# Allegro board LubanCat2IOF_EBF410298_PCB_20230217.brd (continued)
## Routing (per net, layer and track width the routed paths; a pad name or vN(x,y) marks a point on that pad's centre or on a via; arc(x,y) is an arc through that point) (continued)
VCC3V3_SD: length 187.3
  TOP w0.305: J38.17 18.6,61.13 18.86,60.87 ; v1(22.45,14.04) 22.45,26.87 18.86,30.46 18.86,60.87 ; 18.86,60.87 19.1,61.11 J38.19 ; v1(132.66,13.36) 132.66,23.52 133.38,24.23 v1(136.66,24.23) 140.23,24.23 v1(140.94,23.52)
  BOTTOM w0.305: v1(132.66,13.36) 132.05,13.97 115.14,13.97 112.57,11.4 25.1,11.4 v1(22.45,14.04) ; C28.1 v1(136.66,24.23) ; J4.4 v1(140.94,23.52) C30.1
VCC5V0_SYS: length 188.1
  TOP w0.305: 10.46,61.36 10.46,63.8 10.03,64.23 8.76,64.23 8.46,64.54 8.46,70.8 7.85,71.41 C24.2 R11.2
  ART04 w0.305: v1(7.62,59.61) 5.36,59.61 4.75,60.22 4.75,87.3 5.51,88.06 8.81,88.06 9.4,88.64 9.4,94 10.13,94.74 17.55,94.74 18.87,96.06 29.72,96.06 30.33,96.67 30.33,97.94 30.94,98.55 46.91,98.55 47.65,97.81 54.1,97.81 54.94,98.65 108.08,98.65 108.51,98.22 109.86,98.22 110.55,98.9 113.61,98.9 114.05,98.47 118.31,98.47 118.61,98.77 125.15,98.77 125.58,98.34 128.67,98.34 128.86,98.53 131.87,98.53 132.79,97.61 v1(135.52,97.61)
  BOTTOM w0.305: R4.1 v1(135.52,97.61)
VCC5V0_USB: length 13.2
  TOP w0.305: v1(11.53,73.21) C140.2 R235.2
  ART04 w0.305: v1(129.09,96.97) 129.07,96.99 v1(125.52,96.99)
  BOTTOM w0.305: C159.1 11.55,73.22 v1(11.53,73.21)
  vias: v1(14.07,77.26) v1(14.07,76.26) v1(15.07,77.26) v1(15.07,76.26) v1(31.12,86.66) v1(31.12,85.66) v1(32.12,86.66) v1(32.12,85.66) v1(117.47,82.44) v1(118.47,82.44) v1(119.47,82.44) v1(124.52,97.97) v1(124.52,96.97) v1(129.09,97.97) v1(130.09,96.99)
VCC5V0_USB20_HOST2: length 11.6
  BOTTOM w0.508: U24.1 125.41,93.59 C144.1 C145.1 125.34,91.72 125.65,91.41 128.14,91.41 128.7,90.85 128.7,90.14 129.31,89.53 129.31,87.72 J19.10
VCC5V0_USB20_HUB: length 38.3
  TOP w0.305: J20.7 111.1,90.42 110.8,90.72 103.81,90.72 103.5,91.03 103.5,93.72 103.2,94.03 101.22,94.03 100.71,94.53 100.71,96.9 v1(101.47,97.66)
  TOP w0.508: J20.7 J20.1 111.25,85.35 C164.1 C165.1 C162.1 C161.1 114.37,81.39 U29.1
  BOTTOM w0.305: C155.1 101.46,97.72 101.47,97.71 ; 101.47,97.71 v1(101.47,97.66) ; 101.47,97.71 103.51,97.71 104,98.21 C154.1 104.61,97.74 106.07,97.74 106.45,97.36 U28.19
VCC5V0_USB30_HOST: length 5.1
  BOTTOM w0.508: U26.1 129.98,93.59 C148.1 C149.1 129.91,90.45 J19.1
VCC_1V8: length 128.7
  TOP w0.305: L14.2 v1(79.81,39.8) ; Q1.1 v1(28.64,27.5) ; U6.8 v1(33.02,34.77) ; J38.13 17.6,61.13 17.86,60.87 18.1,61.11 J38.15 ; L10.2 v1(60.29,38.62) ; Q2.1 v1(24.83,27.5)
  TOP w0.381: v1(16.91,36.29) 16.91,58.86 17.86,59.82 17.86,60.87
  ART03 w0.381: v1(60.29,38.62) 60.29,39.09 59.52,39.85 35.71,39.85 34.9,39.04 34.9,36.65 v1(33.02,34.77) 33.02,28.9 32.64,28.52 29.65,28.52 v1(28.64,27.5)
  ART04 w0.381: v1(60.29,38.62) 60.29,37.84 60.9,37.23 79.2,37.23 79.81,37.84 v1(79.81,39.8)
  BOTTOM w0.305: v1(28.64,27.5) 28.64,27.04 R45.1 28.48,25.98 25.7,25.98 25.28,26.4 R46.1 24.83,27.04 v1(24.83,27.5)
  BOTTOM w0.381: C22.1 v1(33.02,34.77) C23.1 ; 20.33,35.75 19.79,36.29 v1(16.91,36.29) ; 20.33,35.75 R24.1 ; 20.33,35.75 20.9,36.32 31.72,36.32 32.21,35.84 32.21,34.81 C23.1 ; C23.1 R25.1
VCCA_1V8: length 23.4
  TOP w0.305: J38.14 17.85,71.61 v1(18.1,71.87) 18.35,71.62 J38.16
  BOTTOM w0.305: R219.1 26.27,70.78 25.66,70.17 25.66,65.76 25.08,65.18 22.58,65.18 21.97,65.79 21.97,70.56 21.36,71.17 18.81,71.17 v1(18.1,71.87)
VCCIO_ACODEC: length 45.7
  TOP w0.305: J38.23 20.1,63.64 v1(19.84,63.9) 19.6,63.67 J38.21 ; v1(38.18,77.39) 37.77,76.98 31.29,76.98 30.63,76.32 v1(25.85,76.32)
  BOTTOM w0.305: v1(25.85,76.32) 25.85,74.67 25.15,73.96 24.13,73.96 22.86,72.69 17.75,72.69 17.14,72.08 17.14,70.4 18.03,69.52 18.03,64.51 18.64,63.9 v1(19.84,63.9) ; R213.1 v1(38.18,77.39) 38.18,84.71 R210.1
VDD_3V3: length 85.3
  TOP w0.305: v1(59.29,38.62) 59.29,41.46 L11.2 ; L12.2 v1(58.38,52.31) ; C21.1 v1(4.57,23.8) 4.57,22.93 4.27,22.63 3.38,22.63 3.07,22.93 U12.5 ; R6.2 C14.2 9.91,43.47 10.46,42.92 10.46,33.42 ; R33.1 v1(41.91,56.91) ; L7.2 v1(59.94,20.75) ; U9.5 v1(33.27,20.58) ; U35.5 v1(144.08,64.88) ; U10.5 v1(25.78,20.58) ; U4.5 7.26,22.96 7.57,22.65 8.46,22.65 8.76,22.96 C17.1 v1(9.53,24.57) ; L15.2 v1(79.81,42.46) ; L6.1 v1(40.64,23.41) ; R35.1 v1(43.43,56.91) ; L5.1 v1(48.26,23.41) ; L16.2 v1(78.83,52.31)
  TOP w0.508: 12,16.43 J3.5 12,14.97
  PWR05 w0.508: J3.5 12.73,15.7 ; J3.5 11.27,15.7 ; J3.5 12,16.43 ; J3.5 12,14.97
  BOTTOM w0.305: R47.1 v1(30.47,24.93) ; v1(1.8,52.51) 4.13,52.51 4.44,52.82 R2.2 ; 62.12,73.83 62.42,73.53 Q8.1 61.97,72.4 R181.1 ; 62.12,73.83 62.87,74.58 v1(62.87,78.66) ; 62.12,73.83 59.42,73.83 59.12,73.53 ; C40.1 v1(25.78,20.58) ; R178.1 58.67,72.4 Q6.1 59.12,73.53 ; 59.12,73.53 58.81,73.83 56.63,73.83 56.32,73.53 56.32,71.98 56.02,71.67 R180.1 ; R72.1 v1(15.71,87.85) ; R48.1 v1(24.9,24.93) ; v1(7.65,78.82) 7.65,77.69 7.35,77.38 R236.2 ; R31.1 v1(140.22,97.35) ; C37.1 v1(33.27,20.58) ; R66.2 v1(150.5,95.86) ; R146.1 93.48,61.8 94.08,62.4 96.03,62.4 96.64,61.8 R147.1 96.64,60.94 v1(96.6,60.91) ; R32.1 v1(146.81,95.83)
  vias: v1(9.02,32.64) v1(9.02,31.64) v1(10.02,32.64) v1(10.02,31.64) v1(11.02,32.64) v1(11.02,31.64) v1(20.22,79.94) v1(20.22,78.94) v1(95.31,21.68) v1(96.31,21.68) v1(142.64,13.3) v1(142.64,12.3) v1(143.08,65.88) v1(143.64,13.3) v1(143.64,12.3) v1(144.08,65.88) v1(144.71,41.91) v1(145.71,41.91)
VDD_3V3_EDP_LCD: length 32.5
  TOP w0.305: J29.12 152.81,22.05 153.03,22.27 152.76,22.55 J29.13 ; R187.1 v1(149.22,20.75)
  TOP w0.508: 153.03,22.27 v1(153.39,22.27) 155.57,22.27 156.08,21.76 156.08,13.69 155.45,13.05 149.1,13.05 148.59,13.56 C184.1 C183.1 147.5,14.21 U37.1
  BOTTOM w0.305: v1(153.39,22.27) 153.39,21.05 153.09,20.75 v1(149.22,20.75)
VDD_3V3_EDP_TP: length 29
  TOP w0.305: R193.1 R194.1 C203.1 v1(99.31,18.61)
  BOTTOM w0.381: v1(99.31,18.61) v1(99.31,17.61) 100.08,16.84 100.08,13.23 100.84,12.47 112.19,12.47 112.95,13.23 J28.1
VDD_5V: length 62.1
  TOP w0.305: U10.3 v1(27.05,22.95) ; 10.06,47.37 10.06,57.14 9.75,57.44 C2.2 R1.2 ; v1(144.08,68.72) 143.98,68.82 U36.5 ; U34.5 v1(144.08,60.82) ; U33.5 v1(144.08,57.52) ; U9.3 v1(34.54,22.95)
  TOP w0.508: J3.3 16,16.43 ; J3.3 16.73,15.7 ; J3.3 16,14.97 ; J3.3 15.27,15.7
  BOTTOM w0.305: 49.68,77.69 51.05,76.32 51.05,74.24 51.51,73.78 54.64,73.78 Q7.1 ; 27.05,22.2 v1(27.05,22.95) C41.1 ; 27.05,22.2 27.63,21.61 34.11,21.61 34.54,22.04 v1(34.54,22.95) C38.1 ; 27.05,22.2 26.44,21.59 16.61,21.59 16,20.98 J3.3
  vias: v1(9.02,46.61) v1(9.02,45.61) v1(10.02,46.61) v1(10.02,45.61) v1(11.02,46.61) v1(11.02,45.61) v1(28.38,81.72) v1(29.38,81.72) v1(29.38,80.72) v1(47.01,78.63) v1(47.01,77.63) v1(48.01,78.63) v1(48.01,77.63) v1(119.86,65.68) v1(119.86,64.68) v1(120.86,65.68) v1(120.86,64.68) v1(121.86,65.68) v1(121.86,64.68) v1(133.13,59.59) v1(133.13,58.59) v1(134.13,59.59) v1(134.13,58.59) v1(135.1,59.59) v1(135.13,58.59) v1(143.08,69.72) v1(143.08,61.82) v1(143.08,58.52) v1(143.59,37.24) v1(144.08,69.72) v1(144.08,61.82) v1(144.08,58.52) v1(144.71,38.24) v1(144.71,37.24)
VDD_CAM0_5V: length 9.2
  TOP w0.508: C171.1 C170.1 147.5,57.52 U33.1
  BOTTOM w0.305: J22.2 149.36,51.78 ; J22.1 149.36,51.28 ; J22.3 149.36,52.28
  vias: v1(149.28,57.54) v1(150.28,57.54)
VDD_CAM1_5V: length 3
  TOP w0.508: U36.1 147.38,68.82 C174.1 C175.1
  vias: v1(149.28,69.01) v1(150.28,69.01)
VDD_LCD0_3V3: length 12.2
  TOP w0.305: J23.4 150.61,65.93 150.34,66.19 150.58,66.43 J23.5
  TOP w0.508: U35.1 147.52,64.88 C191.1 147.58,65.96 C185.1 C190.1 v1(149.27,65.97) 149.49,65.97 149.71,66.19 150.34,66.19
  BOTTOM w0.305: R167.1 R222.1 147.46,66.27 147.76,65.97 v1(149.27,65.97)
VDD_LCD0_5V: length 8.5
  TOP w0.508: U34.1 147.52,60.82 C187.1 147.58,61.9 C188.1 C186.1 150.9,61.9 151.51,62.51 151.51,63.8
VDD_LCD1_3V3: length 10.8
  TOP w0.305: R223.1 v1(146.71,46.15) ; U40.1 147.52,43.04 C198.1 147.57,43.11 C196.1 C199.1 ; R224.1 v1(146.71,47.24)
  BOTTOM w0.305: v1(146.71,47.24) v1(146.71,46.15) 147.37,45.49 147.37,44.52 147.68,44.22 v1(149.35,44.22)
VDD_LCD1_5V: length 6.5
  TOP w0.508: U39.1 147.52,38.97 C195.1 147.58,40.05 C197.1 C194.1 151.08,40.06
BAT_RTC: length 14
  BOTTOM w0.381: D21.1 22.67,80.13 C67.1 21.97,79.43 21.97,78.41 20.73,77.16 20.73,74.01 20.29,73.58 17.71,73.58 17.36,73.93 D24.2 17.36,75.77 J16.1
CAM0_NRST: length 109.6
  TOP w0.173: J38.158 v1(53.85,68.74)
  ART03 w0.16: v1(146.69,59.99) 146.15,59.46 136.45,59.46 135.76,60.14 130.91,60.14 130.56,60.5 130.56,63.67 126.49,67.74 104.75,67.74 101.83,64.82 71.12,64.82 69.49,66.44 54.71,66.44 54.39,66.76 54.39,68.19 v1(53.85,68.74)
  BOTTOM w0.173: v1(146.69,59.99) 146.69,60.88 147.59,61.78 J22.22
CAM0_PWDN: length 114.2
  TOP w0.173: v1(53.85,67.74) 53.35,68.24 J38.156
  ART03 w0.16: v1(53.85,67.74) 53.85,66.47 54.25,66.06 69.34,66.06 70.96,64.44 101.98,64.44 104.9,67.36 126.33,67.36 129.97,63.72 129.97,56.77 130.96,55.77 145.54,55.77 v1(146.3,56.54)
  BOTTOM w0.173: J22.15 149.17,58.28 148.72,57.83 146.65,57.83 146.3,57.49 v1(146.3,56.54)
CAM0_PWR_EN: length 89.2
  TOP w0.173: R174.1 v1(140.6,58.59) ; J38.309 v1(93.1,63.93) ; v1(137.01,43.68) 136.37,43.05 113.67,43.05 113.26,43.46 113.26,62.12 v1(114.97,63.83)
  BOTTOM w0.173: v1(137.01,43.68) 137.01,46.07 137.68,46.74 140.8,46.74 141.05,46.99 141.05,58.14 v1(140.6,58.59) ; v1(93.1,63.93) 96.42,63.93 97.69,62.66 113.8,62.66 v1(114.97,63.83)
CAM1_NRST: length 120.2
  TOP w0.173: J38.162 v1(54.85,68.74)
  ART03 w0.16: v1(54.85,68.74) 55.36,68.22 55.36,67.48 55.68,67.16 70.69,67.16 70.92,67.39 70.92,75.83 71.77,76.68 93.83,76.68 94.64,77.49 94.64,80.13 97.87,83.36 115.57,83.36 116.94,84.73 134.72,84.73 135.29,85.3 151.19,85.3 152.65,83.84 v1(152.65,79.98)
  BOTTOM w0.173: J24.22 v1(152.65,79.98)
CAM1_PWDN: length 126.9
  TOP w0.173: v1(54.88,67.88) 54.35,68.41 J38.160
  ART03 w0.16: v1(54.88,67.88) 54.88,67.17 55.2,66.85 70.98,66.85 71.3,67.17 71.3,75.67 71.98,76.35 93.96,76.35 94.97,77.36 94.97,80 97.14,82.17 106.4,82.17 107.27,83.03 115.71,83.03 117.08,84.4 134.86,84.4 135.24,84.79 151,84.79 152.15,83.64 152.15,79.74 152.47,79.42 v1(153.71,79.42)
  BOTTOM w0.173: v1(153.71,79.42) 154.13,79.01 154.13,76.47 153.78,76.12 153.26,76.12 152.9,76.48 J24.15
CAM1_PWR_EN: length 95.3
  TOP w0.173: J38.307 v1(92.6,60.91) ; v1(139.6,63.55) 139.98,63.93 139.98,68.26 R185.1
  ART03 w0.16: v1(111.31,41.19) 111.31,56.93 108.66,59.58 93.92,59.58 v1(92.6,60.91)
  BOTTOM w0.173: v1(139.6,63.55) 139.6,62.05 141.55,60.1 141.55,46.67 141.2,46.33 138.22,46.33 137.87,45.98 137.87,43.06 137.53,42.72 134.37,42.72 132.84,41.19 v1(111.31,41.19)
CAN1_H: length 7.4
  TOP w0.305: U9.7 35.81,17.95 35.51,17.65 35.51,17.11 R39.1 35.56,16.57 35.56,13.86 35.86,13.56 J5.1
CAN1_L: length 7.6
  TOP w0.305: U9.6 34.54,18.08 35.05,17.57 35.05,17.06 R39.2 35.1,16.51 35.1,13.86 34.8,13.56 J5.2
CAN1_RX_M1: length 87.2
  TOP w0.173: J38.275 v1(84.6,63.93) ; U9.4 33.27,26.19 33.8,26.72 44.75,26.72 45.1,27.06 v1(45.1,55.91)
  BOTTOM w0.173: v1(45.1,55.91) 45.2,56 66.2,56 72.29,62.1 82.77,62.1 v1(84.6,63.93)
CAN1_TX_M1: length 83.9
  TOP w0.173: J38.273 84.1,53.39 v1(83.62,52.91) ; U9.1 v1(37.08,25.78)
  ART03 w0.16: v1(37.08,25.78) 38.07,24.79 76.48,24.79 77.42,25.73 77.42,49.91 78.63,51.12 81.84,51.12 v1(83.62,52.91)
CAN2_H: length 7.5
  TOP w0.305: 29.59,13.56 28.22,13.56 27.91,13.86 27.91,16.54 R42.1 27.89,17.11 27.89,17.65 28.32,18.08 U10.7
CAN2_L: length 7.5
  TOP w0.305: U10.6 27.05,18.08 27.43,17.7 27.43,17.06 R42.2 27.46,16.54 27.46,13.86 27.15,13.56 J5.4
CAN2_RX: length 6.7
  TOP w0.173: Q2.3 U10.4 v1(25.78,22.95)
  BOTTOM w0.173: R48.2 v1(25.78,22.95)
CAN2_RX_M0: length 79.6
  TOP w0.173: v1(43.48,28.29) 43.48,55.85 v1(43.43,55.91) ; J38.172 v1(59.35,68.74) ; Q2.2 v1(26.73,27.5)
  ART03 w0.16: v1(43.35,67.74) 43.92,68.3 43.92,69.82 44.35,70.25 58.67,70.25 59.35,69.58 v1(59.35,68.74)
  BOTTOM w0.173: v1(43.35,67.74) 42.9,67.29 42.9,56.6 43.43,56.07 v1(43.43,55.91) ; R46.2 26.73,27.04 v1(26.73,27.5) 27.52,28.29 v1(43.48,28.29)
CAN2_TX: length 6.7
  TOP w0.173: v1(29.59,22.95) U10.1 Q1.3
  BOTTOM w0.173: R47.2 v1(29.59,22.95)
CAN2_TX_M0: length 78.2
  TOP w0.173: v1(44.59,27.45) 44.59,32.13 44.58,32.14 44.58,56.38 v1(45.1,56.91) ; v1(59.35,67.74) 59.85,68.24 J38.174 ; Q1.2 v1(30.54,27.5)
  ART03 w0.16: v1(59.35,67.74) 58.8,68.29 58.8,69.52 58.47,69.85 44.67,69.85 44.35,69.53 44.35,67.74 v1(44.35,67.74)
  BOTTOM w0.173: R45.2 30.54,27.04 v1(30.54,27.5) 44.54,27.5 v1(44.59,27.45) ; v1(45.1,56.91) 44.35,57.66 v1(44.35,67.74)
CC1: length 5.1
  TOP w0.173: J36.A5 25.05,96.66 v1(24.57,97.14)
  BOTTOM w0.173: D27.2 v1(24.57,97.14)
CC2: length 5.2
  TOP w0.173: v1(22.67,97.14) 22.05,96.52 J36.B5
  BOTTOM w0.173: D27.1 v1(22.67,97.14)
CTP0_INT: length 118.2
  TOP w0.173: J38.173 59.1,59.41 v1(59.6,58.91) ; J23.11 v1(153.96,69.43)
  ART03 w0.16: v1(153.96,69.43) 154.69,70.15 155.23,70.15 155.55,69.83 155.55,68.36 155.23,68.04 151.28,68.04 150.75,67.51 148.44,67.51 148.06,67.88 v1(143.08,67.88)
  BOTTOM w0.173: v1(153.96,69.43) 152.74,69.43 151.82,68.5 148.71,68.5 R167.2 ; v1(59.6,58.91) 65.51,58.91 73.13,66.52 92.56,66.52 94.34,68.3 96.49,68.3 98.8,65.99 103.02,65.99 103.5,65.5 118.05,65.5 120.08,67.53 142.74,67.53 v1(143.08,67.88)
CTP0_RST: length 115.7
  TOP w0.173: v1(154.96,69.43) 154.46,69.93 J23.12 ; J38.171 v1(58.6,60.91)
  ART03 w0.16: v1(131.45,69.72) 131.96,69.21 147.45,69.21 148.16,68.5 154.03,68.5 v1(154.96,69.43)
  BOTTOM w0.173: v1(131.45,69.72) 114.63,69.72 113.49,68.58 103.84,68.58 102.7,67.44 99.85,67.44 97.21,70.08 73.64,70.08 65.39,61.83 59.53,61.83 v1(58.6,60.91) ; v1(154.96,69.43) 154.47,68.93 153.09,68.93 151.67,67.52 148.74,67.52 R222.2
CTP1_INT: length 101
  TOP w0.173: v1(112.97,63.83) 112.38,63.24 112.38,42.79 112.98,42.19 139.04,42.19 139.62,42.77 139.62,46.36 139.97,46.7 148.03,46.7 R223.2 149.13,46.69 J26.11 ; J38.255 v1(79.6,63.93)
  BOTTOM w0.173: v1(79.6,63.93) 80.84,65.17 97.16,65.17 97.61,64.72 101.78,64.72 102.67,63.83 v1(112.97,63.83)
CTP1_RST: length 87.7
  TOP w0.173: J26.12 148.63,47.19 R224.2 148,47.82 140.29,47.82 v1(139.83,47.36) ; J38.257 v1(80.1,53.39)
  BOTTOM w0.173: v1(80.1,53.39) 81.31,54.6 111.57,54.6 114.18,51.98 140.07,51.98 140.41,51.63 140.41,47.94 v1(139.83,47.36)
DGB_RX: length 3.6
  BOTTOM w0.173: J2.2 2.4,16.18 Z1.1 4.96,16.86 R36.1
DGB_TX: length 3.5
  BOTTOM w0.173: J2.1 2.36,18.84 Z2.1 4.96,19.52 R23.1
DSI0_RST: length 100.7
  TOP w0.173: J38.175 v1(59.6,60.91) ; J23.15 v1(150.28,71.43)
  ART03 w0.16: v1(132.45,69.72) 132.93,70.21 132.93,70.89 133.24,71.21 140.11,71.21 140.46,70.86 149.71,70.86 v1(150.28,71.43)
  BOTTOM w0.173: v1(59.6,60.91) 60.11,61.41 65.7,61.41 73.93,69.64 97.03,69.64 99.67,67 103.05,67 104.19,68.14 113.82,68.14 114.81,69.13 131.86,69.13 v1(132.45,69.72)
DSI0_TE: length 110.4
  TOP w0.173: R204.1 146.52,72.06 146.06,71.6 144.01,71.6 143.66,71.94 143.66,75.05 142.98,75.74 142.98,76.31 v1(142.63,76.65) ; J38.169 58.1,59.41 v1(58.6,58.91)
  BOTTOM w0.173: v1(142.63,76.65) 141.89,75.92 134.47,75.92 133.96,75.41 133.96,73.44 133.95,73.43 133.95,68.84 133.15,68.03 115.36,68.03 114.68,67.36 104.65,67.36 103.61,66.32 99.03,66.32 96.57,68.78 94.06,68.78 92.35,67.08 72.8,67.08 65.13,59.41 59.1,59.41 v1(58.6,58.91)
DSI1_RST: length 101.9
  TOP w0.173: J26.15 150.48,48.69 150.24,48.93 139.61,48.93 139.12,48.43 139.12,43.24 138.49,42.62 113.44,42.62 112.8,43.25 112.8,62.66 v1(113.97,63.83) ; J38.259 v1(80.6,63.93)
  BOTTOM w0.173: v1(80.6,63.93) 81.46,64.79 96.95,64.79 97.38,64.36 101.42,64.36 102.63,63.16 113.3,63.16 v1(113.97,63.83)
DSI1_TE: length 79.8
  TOP w0.173: v1(81.07,53.39) 81.1,53.41 J38.261 ; v1(139.83,48.36) R208.1
  BOTTOM w0.173: v1(139.83,48.36) 139.83,51.14 139.48,51.48 113.92,51.48 111.38,54.02 92.94,54.02 92.31,53.4 81.08,53.4 v1(81.07,53.39)
EDP_AUXN: length 5.8
  TOP w0.114: J29.10 150.68,21.05 150.55,20.92 150.12,20.92 149.5,21.54 147.73,21.54 147.56,21.7 147.56,22.13 R188.2 C178.2
EDP_AUXP: length 5.7
  TOP w0.114: J29.9 150.68,20.55 150.55,20.68 150.02,20.68 149.4,21.29 147.73,21.29 147.58,21.15 R187.2 C177.2
EDP_BL_EN: length 143.7
  TOP w0.173: J29.22 v1(150.41,27.05) ; J38.233 v1(74.1,60.91)
  ART03 w0.16: v1(108.19,23.04) 108.81,23.67 108.81,25.6 108.25,26.16 108.25,38.6 106.3,40.56 106.3,45.11 105.87,45.54 101.31,45.54 100.99,45.86 100.99,55.61 100.67,55.93 80.3,55.93 76.67,52.29 72.91,52.29 72.59,52.61 72.59,60.21 72.77,60.4 73.59,60.4 v1(74.1,60.91)
  BOTTOM w0.173: v1(150.41,27.05) 150.41,25.64 149.99,25.22 148.3,25.22 147.98,24.9 147.98,14.52 147.32,13.86 133.3,13.86 132.72,14.45 114.98,14.45 114.63,14.79 114.63,21.06 114.28,21.41 108.54,21.41 108.19,21.75 v1(108.19,23.04)
EDP_BL_PWM: length 131.9
  TOP w0.173: J29.23 149.95,27.55 149.66,27.25 149.66,25.6 149.28,25.22 143.73,25.22 143.27,25.69 143.27,34.12 142.95,34.44 142.95,37.18 141.73,38.4 139.72,38.4 139.31,38.81 134.22,38.81 v1(134.21,38.8) ; J38.177 60.1,58.52 56.67,55.09 56.67,42.9 v1(56.82,42.74)
  BOTTOM w0.173: v1(134.21,38.8) 133.85,39.16 104.14,39.16 103.76,38.78 95.5,38.78 93.85,40.43 80.16,40.43 77.85,42.74 v1(56.82,42.74)
EDP_HPDIN_M0: length 205
  TOP w0.173: v1(31.8,10.23) 31.8,15.54 32.08,15.82 32.08,27.03 32.51,27.45 41.56,27.45 41.91,27.8 v1(41.91,55.91) ; v1(38.35,68.74) 38.85,69.24 J38.98 ; J29.17 v1(150.41,24.55)
  BOTTOM w0.173: v1(150.41,24.55) 148.86,24.55 148.44,24.12 148.44,13.46 147.78,12.8 132.13,12.8 131.52,13.41 116.41,13.41 113.67,10.66 32.23,10.66 v1(31.8,10.23) ; v1(41.91,55.91) 41.75,56.07 39.37,56.07 38.96,56.48 38.96,68.12 v1(38.35,68.74)
EDP_LCD_PWR_EN: length 103
  TOP w0.173: R189.2 139.57,14.27 139.27,14.57 139.27,16.95 139.63,17.3 141.39,17.3 141.73,17.65 141.73,27.35 142.25,27.87 142.25,32.3 142.25,32.3 142.25,32.71 142.25,32.71 142.25,36.94 141.41,37.78 121.6,37.78 120.4,38.99 99.64,38.99 99.29,39.33 99.29,53.36 98.71,53.95 v1(92.1,53.95) ; J38.305 v1(92.1,63.93)
  ART04 w0.16: v1(92.1,53.95) v1(92.1,63.93)
EDP_TP_INT: length 82.4
  TOP w0.173: J38.253 v1(79.1,60.91) ; R193.2 v1(107.57,20.37)
  ART03 w0.16: v1(107.57,20.37) 109.46,20.37 109.78,20.69 109.78,22.83 110.39,23.44 110.39,25.02 109.63,25.78 109.63,39.82 109.35,40.1 109.35,57.3 107.85,58.8 92.86,58.8 91.36,60.3 79.71,60.3 v1(79.1,60.91)
  BOTTOM w0.173: v1(107.57,20.37) 110.49,20.37 110.95,19.91 J28.2
EDP_TP_PWR_EN: length 65.4
  TOP w0.173: R191.1 99.31,27.8 99.83,28.33 v1(111.54,28.33) ; J38.303 v1(91.6,60.91)
  ART03 w0.16: v1(111.54,28.33) 110.69,29.17 110.69,56.74 108.25,59.18 93.33,59.18 v1(91.6,60.91)
EDP_TP_RESET: length 148.2
  TOP w0.173: v1(46.1,58.91) 46.63,58.37 46.63,27.66 47.24,27.05 88.28,27.05 88.62,26.7 88.62,17.29 89.18,16.73 106.58,16.73 106.93,17.08 R194.2 v1(107.57,19.35) ; J38.251 v1(78.6,63.93)
  BOTTOM w0.173: v1(46.1,58.91) 46.89,58.11 58.09,58.11 58.83,57.37 65.66,57.37 71.68,63.39 78.07,63.39 v1(78.6,63.93) ; v1(107.57,19.35) 108.65,19.35 108.99,19.01 108.99,14.66 J28.3
EDP_TX_AUXN: length 163.1
  TOP w0.114: v1(38.05,66.87) 37.88,67.04 arc(37.76,67.22) 37.72,67.42 37.72,68.99 arc(37.74,69.06) 37.78,69.13 37.79,69.14 arc(37.84,69.21) 37.85,69.28 J38.94 ; C178.1 v1(145.55,22.79)
  ART03 w0.102: v1(38.05,66.87) 37.9,66.73 arc(37.8,66.58) 37.77,66.41 37.77,65.78 arc(37.95,65.33) 38.4,65.15 64.76,65.15 arc(66.42,64.82) 67.84,63.87 arc(68.42,63.48) 69.11,63.34 110.69,63.34 arc(112.15,63.05) 113.39,62.23 115.03,60.58 arc(115.46,60.29) 115.96,60.19 124.11,60.19 arc(124.75,59.93) 125.02,59.29 125.02,43.46 arc(125.09,43.28) 125.27,43.21 126.16,43.21 arc(126.7,42.68) 126.16,42.14 125.22,42.14 arc(124.97,41.89) 125.22,41.63 126.16,41.63 arc(126.7,41.1) 126.16,40.57 125.22,40.57 arc(124.97,40.31) 125.22,40.06 126.16,40.06 arc(126.7,39.53) 126.16,38.99 125.22,38.99 arc(124.97,38.74) 125.22,38.48 126.16,38.48 arc(126.7,37.95) 126.16,37.42 125.27,37.42 arc(125.09,37.34) 125.02,37.16 125.02,36.93 arc(125.1,36.75) 125.28,36.67 126.23,36.67 arc(126.57,36.53) 126.71,36.19 126.71,31.95 arc(126.77,31.81) 126.92,31.75 142.67,31.75 arc(143.41,31.44) 143.71,30.7 143.71,23.97 arc(143.75,23.89) 143.83,23.85 arc(143.91,23.82) 143.94,23.74 143.94,23.46 arc(143.91,23.38) 143.83,23.35 arc(143.75,23.31) 143.71,23.23 143.71,22.92 arc(143.92,22.43) 144.4,22.23 144.78,22.23 arc(144.98,22.27) 145.14,22.38 v1(145.55,22.79)
EDP_TX_AUXP: length 163.3
  TOP w0.114: J38.92 37.35,69.28 arc(37.36,69.21) 37.41,69.14 37.42,69.13 arc(37.46,69.06) 37.48,68.99 37.48,67.42 arc(37.44,67.22) 37.32,67.04 v1(37.15,66.87) ; C177.1 v1(145.55,21.39)
  ART03 w0.102: v1(145.55,21.39) 145.14,21.8 arc(144.98,21.91) 144.78,21.95 144.4,21.95 arc(143.72,22.23) 143.43,22.92 143.43,30.7 arc(143.21,31.24) 142.67,31.47 126.92,31.47 arc(126.58,31.61) 126.43,31.95 126.43,36.19 arc(126.37,36.33) 126.23,36.39 125.28,36.39 arc(124.9,36.55) 124.74,36.93 124.74,37.16 arc(124.9,37.54) 125.27,37.7 126.16,37.7 arc(126.42,37.95) 126.16,38.2 125.22,38.2 arc(124.69,38.74) 125.22,39.27 126.16,39.27 arc(126.42,39.53) 126.16,39.78 125.22,39.78 arc(124.69,40.31) 125.22,40.85 126.16,40.85 arc(126.42,41.1) 126.16,41.35 125.22,41.35 arc(124.69,41.89) 125.22,42.42 126.16,42.42 arc(126.42,42.68) 126.16,42.93 125.27,42.93 arc(124.9,43.09) 124.74,43.46 124.74,59.29 arc(124.56,59.73) 124.11,59.91 115.96,59.91 arc(115.35,60.04) 114.84,60.38 113.19,62.03 arc(112.04,62.8) 110.69,63.06 69.11,63.06 arc(68.32,63.22) 67.64,63.67 arc(66.32,64.56) 64.76,64.87 38.4,64.87 arc(37.75,65.14) 37.49,65.78 37.49,66.33 arc(37.45,66.53) 37.34,66.69 v1(37.15,66.87)
EDP_TX_D0N: length 168.3
  TOP w0.114: J29.6 150.76,19.05 arc(150.69,19.06) 150.62,19.1 150.61,19.12 arc(150.54,19.16) 150.47,19.18 149.82,19.18 arc(149.69,19.12) 149.64,19 arc(149.59,18.87) 149.46,18.82 149.36,18.82 arc(149.24,18.87) 149.18,19 arc(149.13,19.12) 149.01,19.18 148.91,19.18 arc(148.78,19.12) 148.73,19 arc(148.67,18.87) 148.55,18.82 148.45,18.82 arc(148.32,18.87) 148.27,19 arc(148.22,19.12) 148.09,19.18 145.37,19.18 arc(145.15,19.13) 144.96,19.01 v1(144.78,18.83) ; J38.76 33.35,69.25 arc(33.34,69.17) 33.29,69.11 33.28,69.09 arc(33.24,69.03) 33.22,68.96 33.22,67.42 arc(33.26,67.22) 33.38,67.04 v1(33.55,66.87)
  ART03 w0.102: v1(33.55,66.87) 33.39,66.71 arc(33.28,66.55) 33.24,66.36 33.24,66.19 arc(33.41,65.34) 33.89,64.62 34.62,63.89 arc(35.48,63.32) 36.49,63.12 63.98,63.12 arc(65.15,62.88) 66.14,62.22 arc(66.69,61.85) 67.35,61.72 109.39,61.72 arc(110.62,61.47) 111.66,60.78 113.71,58.73 arc(114.9,57.93) 116.3,57.65 121.69,57.65 arc(122.34,57.39) 122.61,56.74 122.61,30.22 arc(122.8,29.76) 123.27,29.56 138.97,29.56 arc(139.61,29.3) 139.88,28.65 139.88,18.77 arc(140.09,18.25) 140.62,18.03 143,18.03 arc(143.08,18.06) 143.11,18.13 arc(143.14,18.2) 143.21,18.23 143.51,18.23 arc(143.58,18.2) 143.61,18.13 arc(143.64,18.06) 143.72,18.03 144.02,18.03 arc(144.09,18.06) 144.12,18.13 arc(144.15,18.2) 144.22,18.23 144.53,18.23 arc(144.6,18.2) 144.63,18.13 arc(144.66,18.06) 144.73,18.03 145.36,18.03 arc(145.53,18.1) 145.59,18.26 145.59,18.93 arc(145.53,19.07) 145.39,19.13 145.29,19.13 arc(145.1,19.09) 144.94,18.99 v1(144.78,18.83)
EDP_TX_D0P: length 168.4
  TOP w0.114: J38.74 32.85,69.28 arc(32.86,69.21) 32.91,69.14 32.92,69.13 arc(32.96,69.06) 32.98,68.99 32.98,67.42 arc(32.94,67.22) 32.83,67.04 v1(32.65,66.87) ; J29.7 150.76,19.55 arc(150.69,19.53) 150.62,19.49 150.61,19.47 arc(150.54,19.43) 150.47,19.42 145.28,19.42 arc(145.09,19.45) 144.94,19.56 v1(144.78,19.72)
  ART03 w0.102: v1(32.65,66.87) 32.81,66.71 arc(32.92,66.55) 32.96,66.36 32.96,66.19 arc(33.15,65.23) 33.69,64.43 34.43,63.69 arc(35.37,63.06) 36.49,62.84 63.98,62.84 arc(65.04,62.62) 65.94,62.02 arc(66.59,61.59) 67.35,61.44 109.39,61.44 arc(110.51,61.22) 111.46,60.58 113.51,58.53 arc(114.79,57.68) 116.3,57.37 121.69,57.37 arc(122.14,57.19) 122.33,56.74 122.33,30.22 arc(122.6,29.56) 123.27,29.28 138.97,29.28 arc(139.41,29.1) 139.6,28.65 139.6,18.77 arc(139.9,18.05) 140.62,17.75 145.36,17.75 arc(145.72,17.9) 145.87,18.26 145.87,18.93 arc(145.73,19.27) 145.39,19.41 145.29,19.41 arc(145.1,19.45) 144.94,19.56 v1(144.78,19.72)
EDP_TX_D1N: length 168.7
  TOP w0.114: J29.3 150.76,17.55 arc(150.69,17.56) 150.62,17.6 150.61,17.62 arc(150.54,17.66) 150.47,17.68 147.03,17.68 arc(146.82,17.64) 146.65,17.52 v1(146.48,17.35) ; J38.80 34.35,69.28 arc(34.34,69.21) 34.29,69.14 34.28,69.13 arc(34.24,69.06) 34.22,68.99 34.22,68.73 arc(34.29,68.57) 34.45,68.5 34.85,68.5 arc(35.08,68.45) 35.28,68.32 arc(35.41,68.12) 35.46,67.89 35.46,67.24 arc(35.47,67.19) 35.49,67.16 v1(35.78,66.87)
  ART03 w0.102: v1(35.78,66.87) 35.62,66.71 arc(35.52,66.54) 35.48,66.35 arc(36.12,64.8) 37.67,64.16 64.32,64.16 arc(65.62,63.9) 66.72,63.16 arc(67.42,62.69) 68.24,62.53 109.57,62.53 arc(111.38,62.17) 112.92,61.14 114.69,59.37 arc(115.16,59.06) 115.7,58.95 123.13,58.95 arc(123.57,58.77) 123.75,58.33 123.75,31.37 arc(123.88,31.04) 124.21,30.91 124.43,30.91 arc(124.61,30.98) 124.69,31.16 124.69,31.54 arc(125.22,32.08) 125.75,31.54 125.75,31.16 arc(125.83,30.98) 126.01,30.91 140.74,30.91 arc(141.41,30.63) 141.68,29.97 141.68,21.56 arc(141.91,21) 142.47,20.77 147.34,20.77 arc(147.53,20.73) 147.7,20.62 147.93,20.39 arc(148.04,20.22) 148.08,20.03 148.08,18.16 arc(147.93,17.81) 147.57,17.66 146.99,17.66 arc(146.8,17.62) 146.64,17.51 v1(146.48,17.35)
EDP_TX_D1P: length 168.6
  TOP w0.114: J38.78 33.85,69.28 arc(33.86,69.21) 33.91,69.14 33.92,69.13 arc(33.96,69.06) 33.98,68.99 33.98,68.73 arc(34.12,68.4) 34.45,68.26 34.85,68.26 arc(34.99,68.23) 35.11,68.15 arc(35.19,68.03) 35.22,67.89 35.22,67.24 arc(35.21,67.19) 35.18,67.16 v1(34.89,66.87) ; J29.4 150.76,18.05 arc(150.69,18.03) 150.62,17.99 150.61,17.97 arc(150.54,17.93) 150.47,17.92 150.04,17.92 arc(149.93,17.96) 149.88,18.08 arc(149.84,18.19) 149.72,18.23 149.47,18.23 arc(149.36,18.19) 149.31,18.08 arc(149.26,17.96) 149.15,17.92 147.03,17.92 arc(146.82,17.96) 146.65,18.07 v1(146.48,18.24)
  ART03 w0.102: v1(34.89,66.87) 35.05,66.71 arc(35.16,66.54) 35.2,66.35 arc(35.92,64.6) 37.67,63.88 64.32,63.88 arc(65.51,63.64) 66.52,62.96 arc(67.31,62.44) 68.24,62.25 109.57,62.25 arc(111.27,61.91) 112.72,60.94 114.5,59.17 arc(115.05,58.8) 115.7,58.67 123.13,58.67 arc(123.37,58.57) 123.47,58.33 123.47,31.37 arc(123.68,30.84) 124.21,30.63 124.43,30.63 arc(124.81,30.79) 124.97,31.16 124.97,31.54 arc(125.22,31.8) 125.48,31.54 125.48,31.16 arc(125.63,30.79) 126.01,30.63 140.74,30.63 arc(141.21,30.44) 141.4,29.97 141.4,21.56 arc(141.71,20.81) 142.47,20.49 147.34,20.49 arc(147.43,20.48) 147.5,20.43 147.74,20.19 arc(147.79,20.12) 147.8,20.03 147.8,18.16 arc(147.74,18) 147.57,17.94 146.99,17.94 arc(146.8,17.97) 146.64,18.08 v1(146.48,18.24)
EXT_PWR_EN: length 44.9
  TOP w0.173: U2.5 v1(1.91,39.54) ; J38.31 22.1,38.89 v1(22.1,38.88)
  BOTTOM w0.173: v1(1.91,39.54) R8.1 4.1,38.88 v1(22.1,38.88)
FAN_CTRL: length 48.1
  TOP w0.173: J38.183 v1(61.6,60.91)
  ART03 w0.16: v1(61.6,60.91) 61.6,61.42 61.28,61.74 31.79,61.74 31.14,62.39 31.14,72.69 v1(32.16,73.72)
  BOTTOM w0.173: R10.1 29.5,73.68 32.12,73.68 v1(32.16,73.72)
FSPI_CLK: length 36.4
  TOP w0.173: U6.6 28.06,32.23 27.71,32.57 27.71,34.4 27.37,34.74 25.4,34.74 24.6,35.54 J38.41
FSPI_CS0N: length 39.5
  TOP w0.173: U6.1 v1(22.1,34.77) ; J38.49 26.6,37.53 27.18,36.95 29.4,36.95 29.9,36.46 v1(29.9,35.23)
  BOTTOM w0.173: v1(29.9,35.23) 22.56,35.23 v1(22.1,34.77)
FSPI_D0: length 56.7
  TOP w0.173: J32.1 30.78,16.86 30.78,23.39 31.39,24 31.39,29.82 31.22,29.99 30.17,29.99 30,30.17 30,30.79 30.17,30.96 U6.5 33.55,30.96 33.78,31.19 33.78,36.85 33.07,37.56 27.45,37.56 27.1,37.91 J38.51
FSPI_D1: length 40.2
  TOP w0.173: v1(29.4,34.26) 29.4,35.97 29.06,36.32 26.64,36.32 26.1,36.86 J38.47 ; U6.2 v1(22.1,33.5)
  BOTTOM w0.173: v1(22.1,33.5) 22.86,34.26 v1(29.4,34.26)
FSPI_D2: length 41.6
  TOP w0.173: J38.43 25.1,35.81 25.63,35.28 27.98,35.28 28.32,34.93 28.32,33.22 v1(28.65,32.89) ; U6.3 v1(22.1,32.23)
  BOTTOM w0.173: v1(28.65,32.89) 22.76,32.89 v1(22.1,32.23) R24.2
FSPI_D3: length 35.2
  TOP w0.173: J38.45 25.6,36.32 26.06,35.86 28.51,35.86 28.85,35.52 28.85,33.93 29.29,33.5 v1(30.35,33.5) U6.7
  BOTTOM w0.173: R25.2 v1(30.35,33.5)
GMAC0_INT: length 71.6
  TOP w0.173: R104.1 v1(74.52,44.12) ; v1(23.6,43.51) 23.1,44 J38.35
  BOTTOM w0.173: v1(23.6,43.51) 24.26,42.85 35.97,42.85 36.63,43.51 73.91,43.51 v1(74.52,44.12)
GMAC0_MCLKINOUT: length 51.8
  TOP w0.173: J38.89 36.6,51.24 v1(36.45,51.09) ; R105.1 v1(74.52,48.18)
  BOTTOM w0.173: v1(36.45,51.09) 61.81,51.09 64.85,48.05 73.02,48.05 R106.1 74.26,48.44 v1(74.52,48.18)
GMAC0_MDC: length 47.7
  TOP w0.173: U18.13 60.82,49.56 60.39,49.13 60.39,48.15 v1(60.88,47.66) ; J38.83 v1(35.1,50.54)
  BOTTOM w0.173: v1(35.1,50.54) 35.11,50.55 59.86,50.55 61.37,49.04 61.37,48.15 v1(60.88,47.66) 60.74,47.8 R101.2
GMAC0_MDIO: length 42.7
  TOP w0.173: v1(60.88,48.66) 61.39,49.16 U18.14 ; v1(35.61,49.56) 35.6,49.57 J38.85
  BOTTOM w0.173: v1(60.88,48.66) 60.72,48.81 R102.2 59.19,49.56 v1(35.61,49.56)
GMAC0_RSTN: length 49.9
  TOP w0.173: v1(57.48,47.27) 57.96,46.78 D22.2 ; J38.37 v1(23.6,48.03)
  BOTTOM w0.173: v1(57.48,47.27) 56.69,48.05 23.63,48.05 v1(23.6,48.03)
GMAC0_RXCLK: length 62.1
  TOP w0.173: R98.1 v1(69.98,41.19) R95.1 ; J38.69 v1(31.6,41.7)
  BOTTOM w0.173: v1(31.6,41.7) 32.1,42.21 36.34,42.21 37.12,42.99 55.61,42.99 56.39,42.21 68.97,42.21 v1(69.98,41.19)
GMAC0_RXD0: length 63.6
  TOP w0.173: R88.2 v1(67.69,41.19) R91.1 ; v1(33.1,40.18) 33.1,43.12 33.3,43.32 34.19,43.32 34.39,43.52 34.39,43.81 34.19,44.01 33.3,44.01 33.1,44.21 33.1,44.5 33.3,44.7 34.19,44.7 34.39,44.91 34.39,45.19 34.19,45.39 33.3,45.39 33.1,45.6 J38.75
  BOTTOM w0.173: v1(33.1,40.18) 33.64,39.64 66.14,39.64 v1(67.69,41.19)
GMAC0_RXD1: length 63.7
  TOP w0.173: R92.1 v1(66.55,41.19) R89.2 ; v1(34.1,40.18) 34.1,41.94 34.27,42.11 35.62,42.11 35.81,42.31 35.81,46.54 35.47,46.88 34.27,46.88 34.1,47.06 J38.79
  BOTTOM w0.173: v1(34.1,40.18) 34.12,40.16 51.19,40.16 51.36,40.33 51.36,41.17 51.56,41.37 51.85,41.37 52.05,41.17 52.05,40.33 52.22,40.16 52.52,40.16 52.73,40.36 52.73,41.2 52.9,41.37 53.19,41.37 53.42,41.15 53.42,40.36 53.62,40.16 65.51,40.16 v1(66.55,41.19)
GMAC0_RXD2: length 62.5
  TOP w0.173: R93.1 v1(65.41,41.19) R97.1 ; J38.71 v1(32.1,40.18)
  BOTTOM w0.173: v1(32.1,40.18) 32.91,40.99 46.18,40.99 46.35,41.16 46.35,41.7 46.6,41.95 48.52,41.95 48.69,41.77 48.69,41.07 48.9,40.86 49.18,40.86 49.38,41.07 49.38,41.77 49.56,41.95 49.9,41.95 50.07,41.77 50.07,41.07 50.28,40.86 50.56,40.86 50.77,41.07 50.77,41.77 50.94,41.95 55.1,41.95 56.37,40.68 64.89,40.68 v1(65.41,41.19)
GMAC0_RXD3: length 62.5
  TOP w0.173: R94.1 v1(64.26,41.19) R90.2 ; J38.73 v1(32.6,41.7)
  BOTTOM w0.173: v1(32.6,41.7) 32.62,41.69 36.79,41.69 37.57,42.47 38,42.47 38.2,42.27 38.2,41.8 38.41,41.6 38.69,41.6 38.9,41.8 38.9,42.27 39.1,42.47 39.38,42.47 39.59,42.27 39.59,41.8 39.79,41.6 40.08,41.6 40.28,41.8 40.28,42.27 40.48,42.47 40.77,42.47 40.97,42.27 40.97,41.8 41.17,41.6 41.46,41.6 41.66,41.8 41.66,42.27 41.86,42.47 42.15,42.47 42.35,42.27 42.35,41.8 42.55,41.6 42.84,41.6 43.04,41.8 43.04,42.27 43.24,42.47 43.53,42.47 43.73,42.27 43.73,41.8 43.93,41.6 44.22,41.6 44.42,41.8 44.42,42.27 44.63,42.47 44.91,42.47 45.11,42.27 45.11,41.8 45.32,41.6 45.6,41.6 45.8,41.8 45.8,42.27 46.01,42.47 55.38,42.47 56.16,41.69 63.77,41.69 v1(64.26,41.19)
GMAC0_RXDV_CRS: length 63.3
  TOP w0.173: J38.77 33.6,46.4 33.8,46.2 34.88,46.2 35.08,46 35.08,42.89 34.9,42.72 33.85,42.72 33.6,42.47 33.6,39.64 v1(34.11,39.12) ; R96.1 v1(68.83,41.19) R99.1
  BOTTOM w0.173: v1(34.11,39.12) 66.76,39.12 v1(68.83,41.19)
GMAC0_TXCLK: length 58.7
  TOP w0.173: J38.65 30.6,44.58 v1(30.1,44.08) ; v1(64.03,46.66) 64.08,46.66 64.18,46.76 U18.20
  BOTTOM w0.173: v1(30.1,44.08) 30.14,44.04 30.67,44.04 30.87,43.84 30.87,43.57 31.08,43.36 31.36,43.36 31.56,43.57 31.56,43.84 31.77,44.04 32.05,44.04 32.26,43.84 32.26,43.57 32.46,43.36 32.74,43.36 32.95,43.57 32.95,43.84 33.15,44.04 33.44,44.04 33.64,43.84 33.64,43.57 33.84,43.36 34.13,43.36 34.33,43.57 34.33,43.84 34.53,44.04 34.82,44.04 35.02,43.84 35.02,43.57 35.22,43.36 35.51,43.36 35.71,43.57 35.71,43.84 35.91,44.04 62.59,44.04 64.03,45.48 64.03,46.61 64.08,46.66 v1(64.03,46.66)
GMAC0_TXD0: length 59.2
  TOP w0.173: v1(61.88,46.66) 62.37,47.15 63.2,47.15 63.61,47.56 U18.18 ; J38.59 v1(29.1,45.64)
  BOTTOM w0.173: v1(61.88,46.66) 61.4,46.17 56.88,46.17 56.03,47.02 36.18,47.02 35.98,46.81 35.98,46.36 35.77,46.16 35.49,46.16 35.28,46.36 35.28,46.81 35.08,47.02 34.8,47.02 34.59,46.81 34.59,46.36 34.39,46.16 34.11,46.16 33.9,46.36 33.9,46.81 33.7,47.02 33.41,47.02 33.21,46.81 33.21,46.36 33.01,46.16 32.72,46.16 32.52,46.36 32.52,46.81 32.32,47.02 32.03,47.02 31.83,46.81 31.83,46.36 31.63,46.16 31.34,46.16 31.14,46.36 31.14,46.81 30.94,47.02 30.64,47.02 30.4,46.78 30.4,46.35 30.23,46.17 29.63,46.17 v1(29.1,45.64)
GMAC0_TXD1: length 58.8
  TOP w0.173: J38.57 28.6,44.6 v1(28.08,44.08) ; v1(63.01,47.66) 63.31,47.96 U18.17
  BOTTOM w0.173: v1(28.08,44.08) 28.57,44.57 62.36,44.57 63.51,45.73 63.51,47.15 v1(63.01,47.66)
GMAC0_TXD2: length 58.6
  TOP w0.173: J38.61 v1(29.6,46.7) ; v1(61.88,47.66) 62.59,48.36 U18.16
  BOTTOM w0.173: v1(29.6,46.7) 26.79,46.7 26.62,46.87 26.62,47.36 26.79,47.53 56.4,47.53 57.24,46.69 60.92,46.69 v1(61.88,47.66)
GMAC0_TXD3: length 58.5
  TOP w0.173: J38.63 v1(30.1,45.64) ; U18.15 61.99,48.76 v1(61.88,48.66)
  BOTTOM w0.173: v1(61.88,48.66) 62.49,48.05 62.49,46.33 61.8,45.64 56.33,45.64 55.47,46.5 39.63,46.5 39.43,46.3 39.43,45.84 39.22,45.64 38.94,45.64 38.73,45.84 38.73,46.3 38.53,46.5 38.25,46.5 38.04,46.3 38.04,45.84 37.84,45.64 37.55,45.64 37.35,45.84 37.35,46.3 37.15,46.5 36.85,46.5 36.68,46.33 36.68,45.81 36.5,45.64 v1(30.1,45.64)
GMAC0_TXEN: length 58.7
  TOP w0.173: J38.55 28.1,45.14 v1(28.08,45.12) ; v1(63.01,46.66) 63.3,46.66 63.8,47.16 U18.19
  BOTTOM w0.173: v1(28.08,45.12) 39.94,45.12 40.14,45.32 40.14,45.59 40.35,45.79 40.63,45.79 40.83,45.59 40.83,45.32 41.04,45.12 41.32,45.12 41.52,45.32 41.52,45.59 41.73,45.79 42.01,45.79 42.22,45.59 42.22,45.32 42.42,45.12 42.7,45.12 42.91,45.32 42.91,45.59 43.11,45.79 43.4,45.79 43.6,45.59 43.6,45.32 43.8,45.12 44.09,45.12 44.29,45.32 44.29,45.59 44.49,45.79 44.78,45.79 44.98,45.59 44.98,45.32 45.18,45.12 62.09,45.12 63.01,46.04 v1(63.01,46.66)
GMAC1_INT: length 64.8
  TOP w0.173: v1(96.49,46.15) 96.49,44.65 95.96,44.12 R132.1 ; J38.179 v1(60.6,60.91)
  ART04 w0.16: v1(96.49,46.15) 96.49,42.28 96.17,41.96 60.6,41.96 60.11,42.45 60.11,60.42 v1(60.6,60.91)
GMAC1_MCLKINOUT_M1: length 61.8
  TOP w0.173: J38.286 87.85,73.18 87.5,73.53 83.91,73.53 v1(83.35,72.96) ; R134.1 v1(94.97,48.18)
  ART04 w0.16: v1(94.97,48.18) 94.29,47.5 94.29,46.26 91.11,43.07 82.12,43.07 78.97,46.22 78.97,51.2 77.6,52.57 77.6,62.15 78.09,62.64 78.09,65.67 76.5,67.26 76.5,68.53 80.94,72.96 v1(83.35,72.96)
  BOTTOM w0.173: R134.1 v1(94.97,48.18)
GMAC1_MDC_M1: length 48
  TOP w0.173: U19.13 81.19,49.56 80.82,49.2 80.82,45.29 v1(81.46,44.66) ; v1(91.85,68.74) 89.63,68.74 89.35,69.02 J38.292
  ART04 w0.16: v1(81.46,44.66) 81.85,44.26 86.64,44.26 87.88,45.51 89.04,45.51 93.09,49.56 93.09,62.48 92.59,62.98 92.59,68 v1(91.85,68.74)
  BOTTOM w0.173: v1(81.46,44.66) 81.42,44.62 R128.2
GMAC1_MDIO_M1: length 44.9
  TOP w0.173: v1(91.85,67.74) 89.18,67.74 88.85,68.07 J38.290 ; v1(81.46,45.66) 81.46,48.69 81.93,49.16 U19.14
  ART04 w0.16: v1(81.46,45.66) 82.06,45.06 84.99,45.06 85.42,45.49 86.74,45.49 87.55,46.3 88.7,46.3 92.05,49.65 92.05,52.99 91.11,53.93 91.11,62.63 91.61,63.14 91.61,64.13 91.85,64.37 v1(91.85,67.74)
  BOTTOM w0.173: R129.2 81.44,45.64 v1(81.46,45.66)
GMAC1_RSTN: length 33.2
  TOP w0.173: J38.181 61.1,60.41 v1(61.6,59.91)
  TOP w0.305: D35.2 v1(78.13,46.78)
  ART04 w0.16: v1(61.6,59.91) 61.6,51.1 63.49,49.2 63.49,46.15 63.99,45.66 77.01,45.66 v1(78.13,46.78)
GMAC1_RXCLK_M1: length 66.9
  TOP w0.173: v1(108.84,41.19) 107.87,41.19 107.7,41.37 107.7,42.04 107.87,42.21 109.14,42.21 109.45,42.52 109.45,54.1 109.25,54.3 105,54.3 104.8,54.5 104.8,55.93 104.63,56.1 103.37,56.1 103.2,56.28 103.2,56.69 103.37,56.87 104.63,56.87 104.8,57.04 104.8,57.73 104.63,57.91 89.44,57.91 88.1,59.25 J38.289 ; R123.1 v1(90.42,41.19) R117.2
  BOTTOM w0.173: v1(90.42,41.19) v1(108.84,41.19)
GMAC1_RXD0_M1: length 68
  TOP w0.173: R118.1 v1(88.14,41.19) R115.2 ; v1(110.06,42.31) 110.62,42.87 110.62,55.29 110.31,55.6 107.87,55.6 107.67,55.8 107.67,57.12 107.47,57.32 107.18,57.32 106.98,57.12 106.98,55.8 106.77,55.6 106.43,55.6 106.22,55.8 106.22,58.67 105.99,58.91 89.86,58.91 89.1,59.66 J38.293
  BOTTOM w0.173: v1(110.06,42.31) 89.26,42.31 v1(88.14,41.19)
GMAC1_RXD1_M1: length 68.3
  TOP w0.173: R119.1 v1(87,41.19) R116.2 ; v1(111.86,42.31) 111.86,57.98 111.18,58.67 107.98,58.67 107.7,58.95 107.7,59.58 107.37,59.91 90.51,59.91 90.1,60.32 J38.297
  BOTTOM w0.173: v1(87,41.19) 88.63,42.83 111.34,42.83 v1(111.86,42.31)
GMAC1_RXD2_M1: length 67.5
  TOP w0.173: R120.1 v1(85.85,41.19) R125.1 ; J38.287 87.6,59.04 89.23,57.41 102.33,57.41 102.59,57.15 102.59,53.79 102.84,53.54 103.23,53.54 103.44,53.74 103.44,55.12 103.64,55.32 103.92,55.32 104.13,55.12 104.13,53.74 104.33,53.54 108.51,53.54 108.84,53.21 v1(108.84,43.35)
  BOTTOM w0.173: v1(108.84,43.35) 88.01,43.35 v1(85.85,41.19)
GMAC1_RXD3_M1: length 67.5
  TOP w0.173: v1(110.06,43.35) 110.06,54.43 109.58,54.91 105.84,54.91 105.49,55.27 105.49,57.98 105.06,58.41 89.72,58.41 88.6,59.53 J38.291 ; R126.1 v1(84.71,41.19) R122.1
  BOTTOM w0.173: v1(110.06,43.35) 109.98,43.35 109.46,43.87 87.38,43.87 v1(84.71,41.19)
GMAC1_RXDV_CRS_M1: length 67.6
  TOP w0.173: R127.1 v1(89.28,41.19) R124.1 ; v1(110.06,41.19) 111.29,42.42 111.29,55.98 110.9,56.36 110.31,56.36 110.11,56.56 110.11,57.53 109.91,57.73 109.62,57.73 109.42,57.53 109.42,56.56 109.22,56.36 108.78,56.36 108.61,56.53 108.61,57.76 108.44,57.93 107.13,57.93 106.96,58.11 106.96,59.15 106.7,59.41 90.25,59.41 89.6,60.05 J38.295
  BOTTOM w0.173: v1(110.06,41.19) 109.46,41.79 89.88,41.79 v1(89.28,41.19)
GMAC1_TXCLK_M1: length 41.8
  TOP w0.173: v1(84.45,46.66) 84.56,46.76 U19.20 ; v1(84.35,68.74) 84.67,68.74 84.85,68.92 J38.274
  ART04 w0.16: v1(84.35,68.74) 84.35,71.13 84.51,71.29 84.97,71.29 85.13,71.13 85.13,55.99 84.97,55.83 84.29,55.83 84.13,55.67 84.13,54.19 84.13,52.26 84.32,52.07 85.18,52.07 85.38,51.88 85.38,51.57 85.23,51.43 84.32,51.43 84.13,51.24 84.13,50.96 84.37,50.72 86.28,50.72 86.46,50.53 86.46,50.08 86.3,49.92 83.8,49.92 83.62,49.73 83.62,49.47 83.8,49.28 85.79,49.28 85.98,49.09 85.98,46.88 85.75,46.66 v1(84.45,46.66)
GMAC1_TXD0_M1: length 41.9
  TOP w0.173: U19.18 84.06,47.56 83.46,46.96 v1(83.46,46.66) ; J38.276 85.35,68.76 84.83,68.24 83.84,68.24 v1(83.35,68.74)
  ART04 w0.16: v1(83.46,46.66) 83.21,46.66 83.21,46.66 83.05,46.66 83.05,46.66 83.04,46.66 80.59,49.12 80.59,54.86 80.4,55.05 79.83,55.05 79.64,55.24 79.64,55.5 79.83,55.69 81.21,55.69 81.37,55.85 81.37,56.17 81.21,56.33 79.83,56.33 79.64,56.52 79.64,56.78 79.83,56.97 81.21,56.97 81.37,57.13 81.37,57.45 81.21,57.61 79.83,57.61 79.64,57.8 79.64,58.07 79.83,58.25 81.21,58.25 81.37,58.41 81.37,58.73 81.21,58.89 79.83,58.89 79.64,59.08 79.64,59.35 79.83,59.53 80.93,59.53 81.09,59.69 81.09,66.47 v1(83.35,68.74)
GMAC1_TXD1_M1: length 41.5
  TOP w0.173: U19.17 83.76,47.96 v1(83.46,47.66) ; v1(84.35,67.74) 85.24,67.74 85.85,68.35 J38.278
  ART04 w0.16: v1(83.46,47.66) 83.5,47.7 85.29,47.7 85.45,47.86 85.45,48.38 85.29,48.54 83.24,48.54 83.08,48.7 83.08,56.17 83.29,56.38 84.45,56.38 84.61,56.54 84.61,56.9 84.42,57.09 82.76,57.09 82.6,57.25 82.6,57.57 82.76,57.73 84.42,57.73 84.61,57.92 84.61,58.18 84.42,58.37 82.76,58.37 82.6,58.53 82.6,58.77 82.79,58.96 84.47,58.96 84.63,59.12 84.63,59.5 84.44,59.68 83.9,59.68 83.72,59.87 83.72,60.14 83.9,60.32 84.44,60.32 84.63,60.51 84.63,60.78 84.44,60.96 83.9,60.96 83.72,61.15 83.72,61.42 83.9,61.6 84.44,61.6 84.63,61.79 84.63,62.91 84.12,63.42 84.1,63.42 84.1,67.49 v1(84.35,67.74)
GMAC1_TXD2_M1: length 42.2
  TOP w0.173: U19.16 82.93,48.36 82.75,48.19 82.75,46.36 v1(83.46,45.66) ; J38.284 87.35,72.65 87.04,72.96 v1(84.35,72.96)
  ART04 w0.16: v1(84.35,72.96) 83.86,72.47 83.86,71.4 81.79,69.33 81.79,68.09 80.11,66.42 80.11,60.91 79.12,59.91 79.12,53.52 80.08,52.56 80.08,48.91 83.34,45.66 v1(83.46,45.66)
GMAC1_TXD3_M1: length 42
  TOP w0.173: v1(82.46,45.66) 82.19,45.92 82.19,48.59 82.37,48.76 U19.15 ; J38.282 86.85,72.12 86.5,72.46 83.85,72.46 v1(83.35,71.96)
  ART04 w0.16: v1(83.35,71.96) 82.81,71.96 79.11,68.26 79.11,62.4 78.61,61.9 78.61,53.31 79.58,52.35 79.58,48.54 v1(82.46,45.66)
GMAC1_TXEN_M1: length 42.1
  TOP w0.173: v1(84.45,45.66) 83.96,46.15 83.96,46.93 84.19,47.16 U19.19 ; v1(83.35,67.74) 83.84,67.24 85.59,67.24 86.35,68.01 J38.280
  ART04 w0.16: v1(83.35,67.74) 83.35,67.09 83.21,66.95 82.3,66.95 82.09,66.75 82.09,66.46 82.28,66.27 83.2,66.27 83.39,66.09 83.39,65.82 83.2,65.63 82.28,65.63 82.09,65.45 82.09,63.18 82.28,62.99 83.02,62.99 83.21,62.8 83.21,62.54 83.02,62.35 82.28,62.35 82.09,62.16 82.09,61.9 82.28,61.71 83.02,61.71 83.21,61.52 83.21,61.26 83.02,61.07 82.28,61.07 82.09,60.88 82.09,60.62 82.28,60.43 83.02,60.43 83.21,60.24 83.21,59.98 83.02,59.79 82.28,59.79 82.09,59.6 82.09,55.19 81.91,55 81.37,55 81.18,54.81 81.18,54.55 81.37,54.36 81.91,54.36 82.09,54.17 82.09,48.33 83.25,47.17 83.26,47.17 83.26,47.16 83.77,47.16 83.97,46.96 83.97,46.14 v1(84.45,45.66)
HDMI_5V: length 12.5
  ART04 w0.762: J21.18 56.86,81.65
  BOTTOM w0.305: 59.78,76.46 59.56,76.25 R179.1 ; 59.78,76.46 59.78,78.53 59.47,78.84 58.34,78.84 58.16,78.66 56.5,78.66 56.2,78.96 J21.18 ; 59.78,76.46 59.99,76.25 R182.1 ; C168.1 v1(58.08,96.32)
  vias: v1(59.08,96.32) v1(60.08,96.32) v1(60.08,95.32)
HDMI_GND_CHASSIS: length 34.8
  ART03 w0.508: J21.G2 52.45,94.6 52.94,95.09 58.46,95.09 58.95,94.6 J21.G4
  BOTTOM w0.173: 58.97,83.23 J21.G3
  BOTTOM w0.508: J21.G1 J21.G2 ; R177.1 58.97,83.23 ; J21.G3 J21.G4
HDMI_TX0N_PORT: length 41.2
  TOP w0.114: J38.198 65.85,71.5 65.72,71.63 65.72,74.38 65.46,74.63 59.85,74.63 59.72,74.77 59.72,75.02 59.44,75.29 59.05,75.29 58.78,75.02 58.78,74.77 58.64,74.63 58.46,74.63 58.32,74.77 58.32,75.02 58.05,75.29 57.66,75.29 57.38,75.02 57.38,74.77 57.25,74.63 57.06,74.63 56.92,74.77 56.92,75.02 56.65,75.29 56.26,75.29 55.98,75.02 55.98,74.77 55.85,74.63 55.66,74.63 55.53,74.77 55.53,75.02 55.25,75.29 54.86,75.29 54.59,75.02 54.59,74.77 54.45,74.63 53.9,74.63 53.73,74.8 53.73,76.44 53.86,76.56 U32.2 U32.9 53.86,78.22 53.72,78.35 53.72,82.97 53.47,83.22 52.4,83.22 52.29,83.34 52.29,83.71 52.4,83.82 53.48,83.82 53.76,84.09 53.76,84.48 53.48,84.76 52.65,84.76 52.51,84.89 52.51,85.08 52.65,85.22 53.48,85.22 53.76,85.49 53.76,85.88 53.48,86.16 52.65,86.16 52.51,86.29 52.51,86.53 52.63,86.65 54.04,86.65 54.82,87.43 55.44,87.43 55.59,87.28 55.59,86.96 55.48,86.84 J21.9
HDMI_TX0P_PORT: length 40.5
  TOP w0.114: J38.196 65.35,71.5 65.48,71.63 65.48,74.28 65.36,74.39 59.75,74.39 59.48,74.67 59.48,74.92 59.34,75.05 59.15,75.05 59.02,74.92 59.02,74.67 58.74,74.39 58.36,74.39 58.08,74.67 58.08,74.92 57.95,75.05 57.76,75.05 57.62,74.92 57.62,74.67 57.35,74.39 56.96,74.39 56.68,74.67 56.68,74.92 56.55,75.05 56.36,75.05 56.23,74.92 56.23,74.67 55.95,74.39 55.56,74.39 55.29,74.67 55.29,74.92 55.15,75.05 54.96,75.05 54.83,74.92 54.83,74.67 54.55,74.39 53.8,74.39 53.49,74.7 53.49,76.44 53.36,76.56 U32.1 U32.10 53.36,78.22 53.48,78.34 53.48,82.87 53.37,82.98 52.3,82.98 52.04,83.24 52.04,83.81 52.3,84.06 53.38,84.06 53.52,84.19 53.52,84.38 53.38,84.52 52.55,84.52 52.27,84.79 52.27,85.18 52.55,85.46 53.38,85.46 53.52,85.59 53.52,85.78 53.38,85.91 52.55,85.91 52.27,86.19 52.27,86.63 52.53,86.89 53.94,86.89 54.72,87.67 54.87,87.67 J21.7
HDMI_TX1N_PORT: length 40.5
  TOP w0.114: J21.6 54.41,88.58 54.2,88.38 arc(54.15,88.24) 54.2,88.1 arc(54.26,87.97) 54.2,87.83 54.07,87.7 arc(53.94,87.64) 53.8,87.7 arc(53.66,87.76) 53.53,87.7 53.12,87.3 51.5,87.3 51.29,87.09 51.29,86.69 arc(51.36,86.53) 51.52,86.46 51.58,86.46 arc(51.81,86.23) 51.58,86 51.52,86 arc(51.29,85.77) 51.52,85.55 51.58,85.55 arc(51.81,85.32) 51.58,85.09 51.52,85.09 arc(51.36,85.02) 51.29,84.86 51.29,84.42 51.01,84.15 50.72,84.15 50.58,84.01 50.58,83.82 50.72,83.69 51.09,83.69 51.37,83.41 51.37,83.03 51.09,82.75 50.72,82.75 50.58,82.62 50.58,82.43 50.72,82.29 51.01,82.29 51.29,82.02 51.29,81.63 51.01,81.35 50.72,81.35 50.58,81.22 50.58,81.03 50.72,80.9 51.01,80.9 51.29,80.62 51.29,80.23 51.01,79.96 50.72,79.96 50.58,79.82 50.58,79.63 50.72,79.5 51.01,79.5 51.29,79.22 51.29,78.34 51.42,78.22 U31.6 U31.5 51.42,76.56 51.29,76.44 51.29,74.11 51.59,73.81 63.78,73.81 64.22,73.37 64.22,71.63 64.35,71.5 J38.192
HDMI_TX1P_PORT: length 39.9
  TOP w0.114: J21.4 54.77,89.74 54.36,89.33 54.36,88.87 53.02,87.54 51.4,87.54 51.05,87.19 51.05,84.52 50.91,84.39 50.62,84.39 50.34,84.11 50.34,83.72 50.62,83.45 50.99,83.45 51.12,83.31 51.12,83.13 50.99,82.99 50.62,82.99 50.34,82.72 50.34,82.33 50.62,82.05 50.91,82.05 51.05,81.92 51.05,81.73 50.91,81.59 50.62,81.59 50.34,81.32 50.34,80.93 50.62,80.65 50.91,80.65 51.05,80.52 51.05,80.33 50.91,80.2 50.62,80.2 50.34,79.92 50.34,79.53 50.62,79.26 50.91,79.26 51.05,79.12 51.05,78.34 50.92,78.22 U31.7 U31.4 50.92,76.56 51.05,76.44 51.05,74.01 51.49,73.57 63.68,73.57 63.98,73.27 63.98,71.63 63.85,71.5 J38.190
HDMI_TX2N_PORT: length 40.9
  TOP w0.114: J38.188 63.35,71.5 63.22,71.63 63.22,72.27 62.97,72.53 50.39,72.53 49.79,73.12 49.79,76.44 49.92,76.56 U31.2 U31.9 49.92,78.22 49.79,78.34 49.79,87.93 arc(49.83,88.04) 49.94,88.08 arc(50.04,88.13) 50.09,88.23 50.09,88.5 arc(50.04,88.61) 49.94,88.65 arc(49.83,88.7) 49.79,88.8 49.79,89.07 arc(49.83,89.18) 49.94,89.22 arc(50.04,89.27) 50.09,89.37 50.09,89.65 arc(50.04,89.75) 49.94,89.8 arc(49.83,89.84) 49.79,89.95 49.79,90.32 50.29,90.83 arc(50.44,90.89) 50.58,90.83 arc(50.73,90.77) 50.88,90.83 50.99,90.94 arc(51.05,91.09) 50.99,91.23 arc(50.93,91.38) 50.99,91.52 51.26,91.79 52.98,91.79 54.01,90.77 54.74,90.77 J21.3
HDMI_TX2P_PORT: length 40.1
  TOP w0.114: J21.1 54.74,91.01 54.11,91.01 53.08,92.03 51.16,92.03 49.55,90.42 49.55,78.34 49.42,78.22 U31.10 U31.1 49.42,76.56 49.55,76.44 49.55,73.02 50.29,72.28 62.87,72.28 62.98,72.17 62.98,71.63 62.85,71.5 J38.186
HDMI_TX_CEC_PORT: length 10.8
  BOTTOM w0.173: J21.13 53.72,83.06 53.72,77.8 D18.2 54.86,76.66 54.86,76.02 54.61,75.76 Q7.3
HDMI_TX_HPD_PORT: length 9.6
  TOP w0.173: R172.2 60.89,76.93 59.9,76.93 R176.1 D15.2 57.24,78.28 56.26,78.28 56.01,78.53 56.01,80.82 55.76,81.07 J21.19
HDMI_TX_HPDIN: length 12.1
  TOP w0.173: J38.184 v1(62.35,68.74) ; R172.1 v1(63.42,77.52)
  BOTTOM w0.173: v1(63.42,77.52) 63.8,77.14 63.8,70.19 v1(62.35,68.74)
HDMI_TXCLKN_PORT: length 40.7
  TOP w0.114: J21.12 54.67,85.12 54.56,85 54.56,79.56 55.23,78.89 55.23,78.34 55.36,78.22 U32.6 U32.5 55.36,76.56 55.23,76.44 55.23,76.23 55.34,76.12 56.79,76.12 arc(56.87,76.16) 56.91,76.25 arc(56.95,76.34) 57.04,76.37 57.36,76.37 arc(57.45,76.34) 57.48,76.25 arc(57.52,76.16) 57.61,76.12 57.93,76.12 arc(58.02,76.16) 58.06,76.25 arc(58.09,76.34) 58.18,76.37 58.5,76.37 arc(58.59,76.34) 58.63,76.25 arc(58.66,76.16) 58.75,76.12 64.24,76.12 64.35,76.23 64.35,79.8 64.68,80.13 66.64,80.13 66.99,79.78 66.99,77.84 66.73,77.58 65.91,77.58 65.78,77.45 65.78,77.26 65.91,77.12 66.62,77.12 66.92,76.82 66.92,76.44 66.67,76.18 65.63,76.18 65.5,76.05 65.5,75.86 65.63,75.73 66.45,75.73 66.72,75.45 66.72,71.63 66.85,71.5 J38.202
HDMI_TXCLKP_PORT: length 41.4
  TOP w0.114: J38.200 66.35,71.5 66.48,71.63 66.48,75.35 66.35,75.48 65.53,75.48 65.26,75.76 65.26,76.15 65.53,76.42 66.57,76.42 66.68,76.54 66.68,76.72 66.52,76.88 65.81,76.88 65.54,77.16 65.54,77.55 65.81,77.82 66.63,77.82 66.75,77.94 66.75,79.68 66.54,79.89 64.78,79.89 64.59,79.7 64.59,76.13 64.34,75.88 55.24,75.88 54.99,76.13 54.99,76.44 54.86,76.56 U32.4 U32.7 54.86,78.22 54.99,78.34 54.99,78.79 54.32,79.46 54.32,86.02 54.57,86.27 J21.10
HDMI_TXDDC_SCL_PORT: length 11.4
  BOTTOM w0.173: Q6.3 58.17,75.75 R179.2 57.67,77.41 D17.2 57.06,78.02 55.12,78.02 54.48,78.66 54.48,82.66 J21.15
HDMI_TXDDC_SDA_PORT: length 12.9
  BOTTOM w0.173: J21.16 56.94,82.8 58.67,81.07 61.85,81.07 62.07,80.85 D16.2 61.97,77.41 R182.2 61.97,75.39 Q8.3
HDMITX_CEC_M0: length 16.8
  TOP w0.173: v1(62.35,67.74) 61.85,68.24 J38.182
  BOTTOM w0.173: v1(62.35,67.74) 61.82,67.2 54.7,67.2 54.36,67.55 54.36,71.43 R180.2 54.11,72.4 Q7.2
HDMITX_SCL: length 8.3
  TOP w0.173: v1(60.35,68.74) 60.5,68.74 60.85,69.08 J38.178
  BOTTOM w0.173: v1(60.35,68.74) 59.62,69.47 58.04,69.47 57.67,69.84 R178.2 57.67,72.4 Q6.2
HDMITX_SDA: length 6.1
  TOP w0.173: J38.180 v1(61.35,68.74)
  BOTTOM w0.173: v1(61.35,68.74) 61.35,71.29 R181.2 60.97,72.4 Q8.2
HP_DET: length 92.7
  TOP w0.173: v1(19.84,65.74) 20.43,65.14 44.25,65.14 44.6,64.8 J38.121
  ART03 w0.16: v1(19.84,65.74) 19.84,69.19 17.23,71.79 17.23,83.07 18.41,84.25 18.41,95.93 18.8,96.31 31.43,96.31 31.75,96.63 31.75,98.28 32.07,98.6 33.2,98.6 33.2,98.6 38.73,98.6 39.12,98.22 39.12,93.42 38.91,93.21 38.91,92.5 v1(39.4,92.01)
  BOTTOM w0.173: R211.1 41.44,93.31 C213.1 41.14,92.18 40.97,92.01 v1(39.4,92.01)
HP_SNS: length 50.7
  TOP w0.173: J38.42 v1(24.85,68.74)
  ART03 w0.203: J25.5 33.32,95.4 33.32,94.76 30.73,92.17 30.73,89.49 29.79,88.54 25.34,88.54 24.58,87.78 22.68,87.78 21.95,87.04 21.95,78.13 23.07,77 23.07,73.36 24.85,71.58 v1(24.85,68.74)
  BOTTOM w0.173: R216.1 41.14,96.15 40.72,95.73 37.82,95.73 37.47,96.07 R212.1 ; 34.74,96.82 J25.5
  BOTTOM w0.203: R216.1 43.78,96.82 J27.5 ; R212.1 34.74,96.82
HPL_OUT: length 21.8
  TOP w0.173: v1(24.85,67.74) 24.35,68.24 J38.40
  TOP w0.203: v1(22.34,76.32) 22.74,76.32 22.94,76.53 22.94,77.82 21.89,78.87 21.89,81.3 21.69,81.5 C214.1
  ART03 w0.203: v1(24.85,67.74) 24.33,68.25 24.33,71.37 22.56,73.15 22.56,76.11 v1(22.34,76.32)
HPR_OUT: length 23.7
  TOP w0.173: v1(24.85,66.74) 25.35,67.24 J38.44
  TOP w0.203: v1(23.85,76.32) 23.5,76.32 23.3,76.53 23.3,77.97 22.25,79.02 22.25,81.25 22.5,81.5 C215.1
  ART03 w0.203: v1(23.85,76.32) 23.62,76.09 23.62,73.59 25.4,71.81 25.4,67.29 v1(24.85,66.74)
HUB_3V3: length 22.2
  TOP w0.305: v1(102.23,94.92) 101.47,95.68 101.47,96.31 v1(102.23,97.07) 102.82,97.66 v1(106.95,97.66) v1(110.1,97.66)
  BOTTOM w0.305: v1(110.1,97.66) R168.2 110.84,99.08 114.5,99.08 115.05,98.53 R169.1 ; C156.1 C157.1 106.95,98.22 v1(106.95,97.66) U28.20 ; R166.2 v1(102.23,94.92) R164.2 ; R165.2 v1(102.23,97.07)
I2C0_SCL: length 46.4
  TOP w0.173: J38.111 42.1,64.25 41.53,64.82 19.76,64.82 v1(18.84,65.74)
  ART03 w0.16: v1(18.84,65.74) 18.29,66.29 18.29,69.27 16.13,71.43 16.13,82.95 v1(15.37,83.71)
  BOTTOM w0.173: U17.6 v1(15.37,83.71)
